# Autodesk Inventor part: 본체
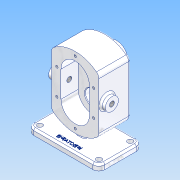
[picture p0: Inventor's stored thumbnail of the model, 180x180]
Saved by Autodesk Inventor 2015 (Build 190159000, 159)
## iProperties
Created: 2019-03
Part Number: 본체
Material: 알루미늄 6061
Document SubType Name: Modeling
Designer: user
Density: 2.7 g/cm^3
Appearance: 알루미늄 - 평지
Mass: 1187.16 g
Surface Area: 719.273 cm^2
Volume: 439.69 cm^3
Author: user
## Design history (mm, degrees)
sketch "스케치1"
  geometry: L1 (-60, 36.5)-(60, 36.5); L2 (60, 36.5)-(60, -36.5); L3 (60, -36.5)-(-60, -36.5); L4 (-60, -36.5)-(-60, 36.5); L5 (-60, 36.5)-(60, -36.5); L6 (60, 36.5)-(-60, -36.5); 1 further point
  constraints: 12 end point, 2 midpoint, 2 parallel, 1 horizontal, 1 perpendicular
  dimensions: "d0" = 120 distance of L2.end L3.end; "d1" = 73 distance of L1.end L2.end
extrude "돌출1" new body sketch "스케치1" distance "d2" = 10; taper "d3" = 0 deg
fillet "모깎기1" dims "d4" = 10
hole "구멍1" diameter "d8" = 9; stored, may be unused: countersink angle "d12" = 90 deg, drill point angle "d14" = 0 deg; dims "d6" = 10, "d7" = 10, "d9" = 6, "d10" = 4, "d11" = 2, "d13" = 8
hole "구멍2" diameter "d17" = 9; stored, may be unused: countersink angle "d21" = 90 deg, drill point angle "d23" = 0 deg; dims "d15" = 10, "d16" = 10, "d18" = 6, "d19" = 4, "d20" = 2, "d22" = 8
hole "구멍3" diameter "d26" = 9; stored, may be unused: countersink angle "d30" = 90 deg, drill point angle "d32" = 0 deg; dims "d24" = 10, "d25" = 10, "d27" = 6, "d28" = 4, "d29" = 2, "d31" = 8
hole "구멍4" diameter "d35" = 9; stored, may be unused: countersink angle "d39" = 90 deg, drill point angle "d41" = 0 deg; dims "d33" = 10, "d34" = 10, "d36" = 6, "d37" = 4, "d38" = 2, "d40" = 8
sketch "스케치2"
  geometry: L1 (50, 36.5)-(-50, 36.5) reference; L2 (-6, -6.5)-(6, -6.5); L3 (6, -6.5)-(6, 36.5); L4 (6, 36.5)-(-6, 36.5); L5 (-6, 36.5)-(-6, -6.5); 2 further points
  constraints: 8 end point, 2 midpoint, 2 parallel, 1 horizontal, 1 perpendicular, 1 point on line
  dimensions: "d42" = 43 distance of L2.end L3.end; "d43" = 12 distance of L2.start L2.end
extrude "돌출2" join sketch "스케치2" distance "d44" = 30; taper "d45" = 0 deg
fillet "모깎기3" dims "d46" = 3
sketch "스케치3"
  geometry: L1 (0, 0)-(100, 0) reference; L2 (90, -122.721)-(90, -33.279); L3 (10, -122.721)-(10, -33.279); A1 r 60 centre (50, -78) between (10, -122.721) and (90, -122.721); A2 r 60 centre (50, -78) between (90, -33.279) and (10, -33.279); 2 further points
  constraints: 6 point on circle, 4 end point, 2 centre point, 2 horizontal alignment, 2 vertical, 1 coincident, 1 midpoint, 1 point on line, 1 vertical alignment
  dimensions: "d47" = 60 radius of A1; "d48" = 78 distance of point (50, 0) A1.centre; "d49" = 60 radius of A2; "d50" = 80 distance between parallel lines of L3 L2
extrude "돌출3" join sketch "스케치3" distance "d51" = 53; taper "d52" = 0 deg
fillet "모깎기4" dims "d53" = 10
sketch "스케치4"
  geometry: L1 (100, 0)-(0, 0) reference; L2 (26, 56)-(26, 100); L3 (74, 100)-(74, 56); A1 r 60 centre (50, 78) between (14, 30) and (86, 30) reference; A2 r 24 centre (50, 100) between (74, 100) and (26, 100); A3 r 24 centre (50, 56) between (26, 56) and (74, 56); 1 further point
  constraints: 4 end point, 4 point on circle, 4 tangent, 2 centre point, 2 vertical alignment, 1 parallel, 1 vertical
  dimensions: "d58" = 24 radius of A2; "d59" = 44 distance of A3.centre A2.centre; "d60" = 22 distance of A2.centre A1.centre
extrude "돌출4" cut sketch "스케치4" distance "d61" = 29; taper "d62" = 0 deg
sketch "스케치5"
  geometry: C1 r 12.5 at (50, 100); A1 r 24 centre (50, 100) between (74, 100) and (26, 100) reference; 1 further point
  constraints: 1 centre point, 1 coincident
  dimensions: "d63" = 25 diameter of C1
extrude "돌출5" cut sketch "스케치5" distance "d64" = 15; taper "d65" = 0 deg
sketch "스케치6"
  geometry: C1 r 12.5 at (50, 56); A1 r 24 centre (50, 56) between (26, 56) and (74, 56) reference; 1 further point
  constraints: 1 centre point, 1 coincident
  dimensions: "d66" = 25 diameter of C1
extrude "돌출6" cut sketch "스케치6" distance "d67" = 15; taper "d68" = 0 deg
chamfer "모따기1" distance "d69" = 1; stored, may be unused: second distance "d70" = 2, angle "d71" = 45 deg
sketch "스케치7"
  geometry: C1 r 19 at (50, -100); A1 r 60 centre (50, -78) between (14, -126) and (86, -126) reference; 1 further point
  constraints: 1 centre point, 1 vertical alignment
  dimensions: "d72" = 38 diameter of C1; "d73" = 100 distance of point (50, 0) C1.centre
extrude "돌출7" join sketch "스케치7" distance "d74" = 17; taper "d75" = 0 deg
node "작업 평면1"
sketch "스케치8"
  geometry: L1 (53.5, 81)-(53.5, 119) reference; L2 (53.5, 114.404)-(52.8, 114); L3 (52.8, 114)-(52.8, 100); L4 (52.8, 114)-(51.613, 114); L5 (52.8, 100)-(53.5, 100); L6 (53.5, 114.404)-(53.5, 100); 1 further point
  constraints: 10 end point, 2 midpoint, 2 point on line, 1 collinear, 1 horizontal, 1 perpendicular, 1 vertical
  dimensions: "d76" = 30 deg angle of L4 L2; "d78" = 0.7 distance of L3.end L5.end; "d79" = 14 distance of L2.end L3.end
revolve "회전1" sketch "스케치8" stored, may be unused: angle "d80" = 90 deg
sketch "스케치9"
  geometry: L1 (52.8, 114)-(52.8, 86) reference; L2 (52.8, 114)-(46.2, 114); L3 (46.2, 114)-(46.2, 100); L4 (46.2, 100)-(52.8, 100); 2 further points
  constraints: 6 end point, 2 midpoint, 2 perpendicular, 1 horizontal, 1 point on line
  dimensions: "d81" = 6.6 distance of L3.end L4.end; "d82" = 14 distance of L2.end L3.end (derived)
revolve "회전2" sketch "스케치9" stored, may be unused: angle "d83" = 90 deg
fillet "모깎기5" dims "d84" = 0.5
hole "구멍5" diameter "d87" = 17; stored, may be unused: countersink angle "d91" = 90 deg, drill point angle "d93" = 0 deg; dims "d85" = 10, "d86" = 10, "d88" = 6, "d89" = 4, "d90" = 2, "d92" = 8
sketch "스케치10"
  geometry: L1 (80, -53)-(0, -53) reference; L2 (118, -10)-(118, -63) reference; C1 r 11 at (40, -39); 1 further point
  constraints: 1 centre point
  dimensions: "d94" = 22 diameter of C1; "d95" = 14 distance from line of C1.centre L1; "d96" = 78 distance from line of L2 C1.centre
extrude "돌출8" join sketch "스케치10" distance "d97" = 8; taper "d98" = 0 deg
fillet "모깎기6" dims "d99" = 3
hole "구멍6" diameter "d102" = 8.376; stored, may be unused: countersink angle "d106" = 90 deg, drill point angle "d108" = 0 deg; dims "d103" = 30, "d104" = 4, "d105" = 2, "d107" = 37.3, "d111" = 10, "d112" = 10
fillet "모깎기7" dims "d109" = 3
fillet "모깎기8" dims "d110" = 3
sketch "스케치11"
  geometry: L1 (19, 100)-(19, 56); L2 (81, 56)-(81, 100); A1 r 24 centre (50, 56) between (26, 56) and (74, 56) reference; A2 r 24 centre (50, 100) between (74, 100) and (26, 100) reference; A3 r 31 centre (50, 100) between (81, 100) and (19, 100); A4 r 31 centre (50, 56) between (19, 56) and (81, 56); 7 further points
  constraints: 6 coincident, 6 point on circle, 4 end point, 2 centre point, 2 tangent, 1 parallel, 1 vertical
  dimensions: "d113" = 31 radius of A3; "d114" = 31 radius of A4
hole "구멍7" sketch "스케치11" at (50, 131), (19, 100), (81, 100), (81, 56), (19, 56), (50, 25) diameter "d116" = 4.134; stored, may be unused: countersink angle "d120" = 90 deg, drill point angle "d122" = 118 deg; dims "d117" = 10, "d118" = 4, "d119" = 2, "d121" = 12
node "작업 평면2"
sketch "스케치12"
  geometry: L1 (-60, 26.5)-(-60, -26.5) reference; L2 (-50, -36.5)-(50, -36.5) reference; 2 further points
  constraints: 1 other
  dimensions: "d124" = 60 distance from line of L1 point (0, -26.5); "d125" = 10 distance from line of point (0, -26.5) L2
feature "엠보싱1" sketch "스케치12" dims "d126" = 0.5, "d127" = 0
node "솔리드1"
mirror "대칭1"
mirror "대칭2"
other parameters: "d123" = 11.5
